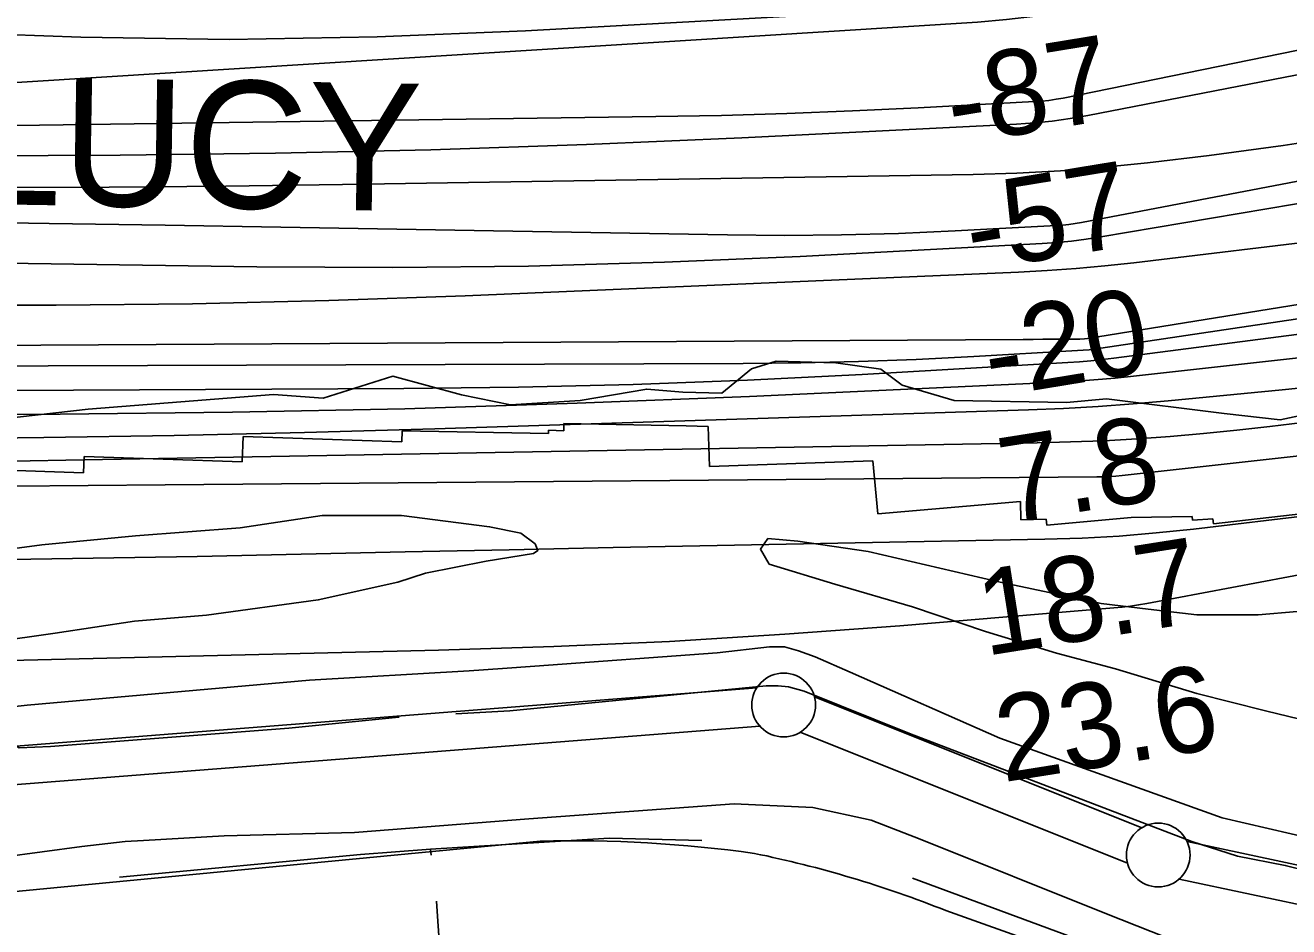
# Model space of a CAD drawing. Extents: x 3508733 to 3546731, y 546897 to 572481.
# Drawn here: x 3535009 to 3536000, y 561954 to 562661 of the extents above; entities that cross this region are included whole.
import ezdxf

# ---------------------------------------------------------------- set-up
doc = ezdxf.new("R2010")
doc.units = 0
for name, color, linetype in [('V-FLOD-BASE', 7, 'Continuous'), ('V-LEVE-TOET', 7, 'Continuous'), ('V-RIVR-EDGE', 7, 'Continuous'), ('V-RIVR-RANG', 7, 'Continuous'), ('V-ROAD-CNTR', 7, 'Continuous'), ('V-RRAP-RVMT', 7, 'Continuous'), ('V-RRAP-RVMT-IDEN', 7, 'Continuous'), ('V-SITE-VEGE', 7, 'Continuous'), ('V-SURV-LINE', 7, 'Continuous'), ('V-TOPO-DPTH', 7, 'Continuous'), ('V-TOPO-MAJR', 7, 'Continuous'), ('V-TOPO-MINR', 7, 'Continuous'), ('V-TOPO-SHOR', 7, 'Continuous'), ('V-TOPO-WATR', 7, 'Continuous')]:
    doc.layers.add(name, color=color, linetype=linetype)

msp = doc.modelspace()

# ---------------------------------------------------------------- linework, layer by layer
at = {"layer": 'V-FLOD-BASE'}
for points in [[(3535346.74, 562120.84), (3535389.06, 562123.27), (3535590.19, 562142.96), (3535599.58, 562142.86), (3535607.8, 562142.19), (3535620.1, 562138.54), (3535702.6, 562105.39), (3535924.4, 562020.89), (3535960.12, 562009.37), (3535997.65, 562001.94), (3536053.9, 561987.85), (3536085.55, 561980.48), (3536112.54, 561977.27), (3536164.23, 561976.16), (3536242.97, 561977.7), (3536287.05, 561979.61)], [(3532710.45, 562040.61), (3532907.8, 562036.26), (3533054.05, 562032.42), (3533261.96, 562026.2), (3533512.77, 562021.89), (3533708.99, 562021.66), (3533810.05, 562022.98), (3533971.6, 562021.93), (3534038.02, 562025.37), (3534206.16, 562037.17), (3534387.26, 562051.78), (3534513.1, 562063.43), (3534724.18, 562080.08), (3534928.17, 562093.28), (3534994.62, 562099.66), (3535003.96, 562094.28), (3535028.65, 562095.2), (3535215.62, 562109.75), (3535302.06, 562118.27), (3535302.12, 562118.28)]]:
    msp.add_lwpolyline(points, dxfattribs=at)
at = {"layer": 'V-LEVE-TOET'}
for points in [[(3536056.52, 562014.26), (3535948.09, 562039.45), (3535773.65, 562101.73), (3535656.09, 562153.45), (3535628.6, 562165.48), (3535615.73, 562170.31), (3535604.6, 562173.36), (3535592.85, 562173.48), (3535551.67, 562168.61), (3535408.81, 562158.32), (3535383.24, 562156.54), (3535357.07, 562154.73), (3535231.86, 562147.19), (3535010.18, 562127.7), (3534833.15, 562108.35), (3534677.93, 562096.41), (3534491.56, 562083.03), (3534318.08, 562065.99), (3534147.58, 562053.63), (3533987.15, 562049.38), (3533933.12, 562050.52)], [(3534380.39, 561953.86), (3534559.73, 561969.66), (3534741.97, 561980.73), (3534928.4, 561999.99), (3535053.12, 562016.94), (3535087.23, 562020.7), (3535101.67, 562021.54), (3535164.94, 562025.2), (3535267.19, 562027.8), (3535404.07, 562038.52), (3535565.16, 562050.39), (3535626.81, 562047.41), (3535672.54, 562037.55), (3535711.16, 562022.47), (3535857.44, 561964), (3535975.05, 561917.57)]]:
    msp.add_lwpolyline(points, dxfattribs=at)
at = {"layer": 'V-RIVR-EDGE'}
msp.add_lwpolyline([(3534866.07, 562338.1), (3535058.23, 562359.84), (3535203.54, 562371.48), (3535242.55, 562368.39), (3535297.22, 562385.66), (3535351.22, 562371.12), (3535389.62, 562363.22), (3535444.26, 562366.69), (3535496.51, 562375.56), (3535524.72, 562373.09), (3535555.33, 562372.42), (3535578.79, 562391.57), (3535598.02, 562397.52), (3535644.84, 562396.21), (3535680.24, 562391.32), (3535697.02, 562378.67), (3535737.81, 562366.56), (3535826.06, 562365.14), (3535857.28, 562368.07), (3535949.71, 562356.43), (3535993.52, 562351.52), (3536065.59, 562366.95)], dxfattribs=at)
at = {"layer": 'V-ROAD-CNTR'}
for points in [[(3535412.83, 562021.11), (3534946.57, 561976.32), (3534572.86, 561951.67), (3534297.18, 561926.9), (3534032.81, 561905.44)], [(3535875.71, 561915.18), (3535731.32, 561966.59)]]:
    msp.add_lwpolyline(points, dxfattribs=at)
for centre, radius, start, end in [((3535436.77, 560972.05), 1049.34, 82.09715, 91.30692), ((3535401.25, 561134.53), 895.13, 68.36224, 78.41314)]:
    msp.add_arc(centre, radius, start, end, dxfattribs=at)
at = {"layer": 'V-RRAP-RVMT'}
for p, q in [((3535304.22, 562334.23), (3535304.53, 562342.94)), ((3535304.53, 562342.94), (3535419.28, 562340.82)), ((3535419.28, 562340.82), (3535419.34, 562343.39)), ((3535419.34, 562343.39), (3535431.32, 562342.98)), ((3535431.32, 562342.98), (3535431.49, 562348.53)), ((3535431.49, 562348.53), (3535527.33, 562346.75)), ((3535527.33, 562346.75), (3535544.61, 562346.15)), ((3535544.61, 562346.15), (3535545.79, 562314.95)), ((3535178.9, 562318.53), (3535179.72, 562338.43)), ((3535179.72, 562338.43), (3535304.22, 562334.23)), ((3535054.51, 562309.97), (3535054.98, 562322.72)), ((3535054.98, 562322.72), (3535178.9, 562318.53)), ((3534931.1, 562314.19), (3535054.51, 562309.97)), ((3535545.79, 562314.95), (3535674, 562319.39)), ((3535674, 562319.39), (3535677.82, 562277.65)), ((3535677.82, 562277.65), (3535789.84, 562287.54)), ((3535789.84, 562287.54), (3535790.11, 562273.09)), ((3535790.11, 562273.09), (3535809.94, 562273.49)), ((3535809.94, 562273.49), (3535810.38, 562268.76)), ((3535810.38, 562268.76), (3535876.7, 562274.81)), ((3535876.7, 562274.81), (3535924.59, 562275.76)), ((3535924.59, 562275.76), (3535924.78, 562272.68)), ((3535924.78, 562272.68), (3535940.9, 562273.76)), ((3535940.9, 562273.76), (3535941.36, 562269.85)), ((3535941.36, 562269.85), (3536021.35, 562279.16))]:
    msp.add_line(p, q, dxfattribs=at)
at = {"layer": 'V-SITE-VEGE'}
for points in [[(3534952.88, 562244.26), (3535021.71, 562253.54), (3535095.22, 562260.44), (3535177.53, 562266.65), (3535241.67, 562276.57), (3535303.94, 562276.53), (3535373.17, 562267.6), (3535397.8, 562262.65), (3535408.88, 562254.31), (3535411.17, 562249), (3535407.62, 562246.69), (3535370.55, 562240.6), (3535322.87, 562231.1), (3535301.06, 562224.27), (3535238.65, 562210.22), (3535150.98, 562198.18), (3535094.54, 562193.47), (3535032.17, 562184.11), (3534982.16, 562176.98)], [(3536009.07, 562116.61), (3535982.11, 562123.35), (3535928.2, 562136.83), (3535864.36, 562156.27), (3535818.08, 562168.49), (3535762.44, 562185.51), (3535705.06, 562204.89), (3535644.14, 562222.55), (3535592.6, 562238.34), (3535585.67, 562250.17), (3535591.63, 562258.33), (3535615.11, 562256.33), (3535670.25, 562248.13), (3535771.65, 562224.78), (3535853.13, 562207.5), (3535890.1, 562203.01), (3535928.24, 562198.51), (3535976.42, 562198.61), (3536006.99, 562201.24)]]:
    msp.add_lwpolyline(points, dxfattribs=at)
at = {"layer": 'V-SURV-LINE'}
for points in [[(3533967.89, 562014.2), (3535582.88, 562141.23)], [(3535628.11, 562134.33), (3535884.95, 562031.5)], [(3535585.23, 562111.32), (3533970.23, 561984.29)], [(3535873.78, 562003.66), (3535616.94, 562106.49)], [(3535920.59, 562020.68), (3536090.87, 561984.55)], [(3536084.63, 561955.21), (3535914.35, 561991.33)]]:
    msp.add_lwpolyline(points, dxfattribs=at)
for centre in [(3535603.97, 562127.84), (3535897.92, 562010.15)]:
    msp.add_circle(centre, 25, dxfattribs=at)
at = {"layer": 'V-TOPO-DPTH'}
for points in [[(3536504.22, 562604.88), (3535853, 562494.94), (3535841.49, 562493.2), (3535829.95, 562491.72), (3535818.36, 562490.64), (3535806.74, 562489.82), (3535616.96, 562479.7), (3535510.41, 562475.1), (3535403.84, 562471.95), (3535297.22, 562470.97), (3535190.57, 562471.44), (3534795.52, 562477.17), (3534753.11, 562477.76), (3534710.7, 562478.3), (3534668.29, 562478.78), (3534625.88, 562479.22), (3534583.15, 562479.64), (3534519.37, 562480.23), (3534455.59, 562480.79), (3534391.82, 562481.3), (3534328.04, 562481.78), (3533592.42, 562487)], [(3536504.22, 562604.88), (3535853, 562494.94), (3535841.49, 562493.2), (3535829.95, 562491.72), (3535818.36, 562490.64), (3535806.74, 562489.82), (3535616.96, 562479.7), (3535510.41, 562475.1), (3535403.84, 562471.95), (3535297.22, 562470.97), (3535190.57, 562471.44), (3534795.52, 562477.17), (3534753.11, 562477.76), (3534710.7, 562478.3), (3534668.29, 562478.78), (3534625.88, 562479.22), (3534583.15, 562479.64), (3534519.37, 562480.23), (3534455.59, 562480.79), (3534391.82, 562481.3), (3534328.04, 562481.78), (3533592.42, 562487)], [(3533862.28, 562416.56), (3534004.12, 562415.25), (3534145.97, 562413.99), (3534287.82, 562412.82), (3534429.66, 562411.71), (3534641.17, 562410.11), (3534677.26, 562409.86), (3534713.36, 562409.65), (3534749.45, 562409.5), (3534785.55, 562409.38), (3534821.64, 562409.34), (3534857.74, 562409.35), (3534893.84, 562409.46), (3534929.93, 562409.62), (3535792.04, 562414.58), (3535799.65, 562414.62), (3535807.25, 562414.67), (3535814.86, 562414.71), (3535822.46, 562414.76), (3535835.37, 562414.83), (3535836.52, 562414.85), (3535839.96, 562414.98), (3535842.49, 562415.15), (3536790.17, 562568.34)], [(3533862.28, 562416.56), (3534004.12, 562415.25), (3534145.97, 562413.99), (3534287.82, 562412.82), (3534429.66, 562411.71), (3534641.17, 562410.11), (3534677.26, 562409.86), (3534713.36, 562409.65), (3534749.45, 562409.5), (3534785.55, 562409.38), (3534821.64, 562409.34), (3534857.74, 562409.35), (3534893.84, 562409.46), (3534929.93, 562409.62), (3535792.04, 562414.58), (3535799.65, 562414.62), (3535807.25, 562414.67), (3535814.86, 562414.71), (3535822.46, 562414.76), (3535835.37, 562414.83), (3535836.52, 562414.85), (3535839.96, 562414.98), (3535842.49, 562415.15), (3536790.17, 562568.34)], [(3536039.54, 562494.04), (3535878.65, 562474.65), (3535856.07, 562472.19), (3535833.47, 562470.09), (3535810.82, 562468.51), (3535788.14, 562467.28), (3535353.95, 562448.85), (3535247.02, 562445.12), (3535140.07, 562442.45), (3535033.09, 562441.39), (3534926.09, 562441.4), (3534762.65, 562442.64), (3534737.36, 562442.83), (3534712.07, 562443.04), (3534686.77, 562443.26), (3534661.48, 562443.48), (3534009.83, 562449.45), (3533932.07, 562450.16)], [(3533932.07, 562450.16), (3534009.83, 562449.45), (3534661.48, 562443.48), (3534686.77, 562443.26), (3534712.07, 562443.04), (3534737.36, 562442.83), (3534762.65, 562442.64), (3534926.09, 562441.4), (3535033.09, 562441.39), (3535140.07, 562442.45), (3535247.02, 562445.12), (3535353.95, 562448.85), (3535788.14, 562467.28), (3535810.82, 562468.51), (3535833.47, 562470.09), (3535856.07, 562472.19), (3535878.65, 562474.65), (3536039.54, 562494.04)], [(3536178.12, 562440.74), (3535863.07, 562399.79), (3535854.08, 562398.72), (3535845.07, 562397.77), (3535836.05, 562397.03), (3535827.01, 562396.41), (3535665.5, 562387.12), (3535575.67, 562382.67), (3535485.82, 562379.17), (3535395.92, 562377.08), (3535305.99, 562375.95), (3534735.27, 562373.24), (3534725.01, 562373.2), (3534714.76, 562373.15), (3534704.51, 562373.11), (3534694.25, 562373.07), (3534490.36, 562372.29), (3534378.15, 562372), (3534265.95, 562371.89), (3534153.75, 562372.08), (3534041.55, 562372.45), (3533601.11, 562374.45)], [(3533601.11, 562374.45), (3534041.55, 562372.45), (3534153.75, 562372.08), (3534265.95, 562371.89), (3534378.15, 562372), (3534490.36, 562372.29), (3534694.25, 562373.07), (3534704.51, 562373.11), (3534714.76, 562373.15), (3534725.01, 562373.2), (3534735.27, 562373.24), (3535305.99, 562375.95), (3535395.92, 562377.08), (3535485.82, 562379.17), (3535575.67, 562382.67), (3535665.5, 562387.12), (3535827.01, 562396.41), (3535836.05, 562397.03), (3535845.07, 562397.77), (3535854.08, 562398.72), (3535863.07, 562399.79), (3536178.12, 562440.74)], [(3536067.23, 562382.22), (3535995.17, 562374.91), (3535905.67, 562366.33), (3535878.3, 562363.97), (3535850.91, 562361.96), (3535823.48, 562360.47), (3535796.04, 562359.32), (3535330.24, 562344.39), (3535227.93, 562341.5), (3535125.61, 562339.12), (3535023.28, 562337.52), (3534920.93, 562336.44), (3534757.58, 562335.33), (3534736.9, 562335.18), (3534716.23, 562335.03), (3534695.55, 562334.87), (3534674.87, 562334.71), (3533882.99, 562328.22)], [(3536067.23, 562382.22), (3535995.17, 562374.91), (3535905.67, 562366.33), (3535878.3, 562363.97), (3535850.91, 562361.96), (3535823.48, 562360.47), (3535796.04, 562359.32), (3535330.24, 562344.39), (3535227.93, 562341.5), (3535125.61, 562339.12), (3535023.28, 562337.52), (3534920.93, 562336.44), (3534757.58, 562335.33), (3534736.9, 562335.18), (3534716.23, 562335.03), (3534695.55, 562334.87), (3534674.87, 562334.71), (3533882.99, 562328.22)], [(3534997.78, 562299.42), (3535058.15, 562299.88), (3535118.53, 562300.38), (3535849.72, 562306.66), (3535854.72, 562306.78), (3535859.71, 562307), (3535864.69, 562307.37), (3535869.66, 562307.85), (3536178.34, 562342.07)]]:
    msp.add_lwpolyline(points, dxfattribs=at)
at = {"layer": 'V-TOPO-MAJR'}
for points in [[(3534936.08, 562655.7), (3535052.41, 562651.55), (3535168.73, 562649.88), (3535285.05, 562651.96), (3535401.37, 562656.52), (3535766.47, 562676.73), (3535783.08, 562678.07), (3535799.6, 562679.98), (3535816.01, 562682.72), (3535832.33, 562686.03), (3536334.06, 562801.04)], [(3534913.7, 562507.22), (3535027.54, 562505.5), (3535118.48, 562504.08), (3535209.42, 562502.62), (3535300.37, 562501.09), (3535391.31, 562499.5), (3535559.98, 562496.5), (3535604.66, 562496.18), (3535649.33, 562496.49), (3535693.98, 562497.74), (3535738.62, 562499.62), (3535818.02, 562503.8), (3535822.94, 562504.16), (3535827.84, 562504.65), (3535832.72, 562505.35), (3535837.58, 562506.17), (3536547.27, 562641.56)]]:
    msp.add_lwpolyline(points, dxfattribs=at)
at = {"layer": 'V-TOPO-MINR'}
for points in [[(3533931.78, 562646.66), (3534007.98, 562642.14), (3534662.9, 562605.64), (3534684.4, 562604.61), (3534705.91, 562603.79), (3534727.43, 562603.29), (3534748.95, 562603.02), (3534770.47, 562603.12), (3534791.99, 562603.52), (3534813.49, 562604.36), (3534834.98, 562605.49), (3535756.08, 562663.44), (3535778.85, 562665.42), (3535801.52, 562668.1), (3535824.04, 562671.86), (3535846.45, 562676.32), (3536721.03, 562872.16)], [(3533939.82, 562567.51), (3534070.5, 562563.77), (3534201.21, 562561.35), (3534331.94, 562559.81), (3534671.43, 562557.52), (3534689.55, 562557.43), (3534707.67, 562557.39), (3534725.78, 562557.4), (3534743.9, 562557.46), (3535083.15, 562559.19), (3535205.19, 562560.64), (3535327.19, 562563.17), (3535449.16, 562567.34), (3535571.09, 562572.61), (3535786.58, 562583.36), (3535800.71, 562584.37), (3535814.79, 562585.78), (3535828.8, 562587.78), (3535842.77, 562590.19), (3536911.98, 562797.95)], [(3533566.37, 562617.21), (3534301.26, 562585.73), (3534368.83, 562583.21), (3534436.41, 562581.18), (3534504.01, 562579.9), (3534571.62, 562579.11), (3534691.63, 562578.37), (3534699.24, 562578.35), (3534706.86, 562578.35), (3534714.47, 562578.41), (3534722.08, 562578.49), (3535503.67, 562589.29), (3535555.12, 562590.3), (3535606.57, 562591.72), (3535657.99, 562593.75), (3535709.4, 562596.18), (3535800.93, 562601.05), (3535806.55, 562601.48), (3535812.14, 562602.07), (3535817.71, 562602.9), (3535823.25, 562603.9), (3536055.11, 562651.06)], [(3533592.42, 562487), (3534328.04, 562481.78), (3534391.82, 562481.3), (3534455.59, 562480.79), (3534519.37, 562480.23), (3534583.15, 562479.64), (3534625.88, 562479.22), (3534668.29, 562478.78), (3534710.7, 562478.3), (3534753.11, 562477.76), (3534795.52, 562477.17), (3535190.57, 562471.44), (3535297.22, 562470.97), (3535403.84, 562471.95), (3535510.41, 562475.1), (3535616.96, 562479.7), (3535806.74, 562489.82), (3535818.36, 562490.64), (3535829.95, 562491.72), (3535841.49, 562493.2), (3535853, 562494.94), (3536504.22, 562604.88)], [(3533680.62, 562539.52), (3534649.1, 562534.39), (3534678.83, 562534.25), (3534708.56, 562534.11), (3534738.29, 562534.01), (3534768.02, 562533.91), (3534891.63, 562533.58), (3534983.17, 562533.58), (3535074.7, 562533.93), (3535166.23, 562534.79), (3535257.76, 562535.99), (3535752.64, 562543.87), (3535786.95, 562544.94), (3535821.21, 562546.72), (3535855.41, 562549.55), (3535889.55, 562553.08), (3535937.85, 562558.82), (3535995.96, 562566.58), (3536053.89, 562575.46)], [(3533862.28, 562416.56), (3534004.12, 562415.25), (3534145.97, 562413.99), (3534287.82, 562412.82), (3534429.66, 562411.71), (3534641.17, 562410.11), (3534677.26, 562409.86), (3534713.36, 562409.65), (3534749.45, 562409.5), (3534785.55, 562409.38), (3534821.64, 562409.34), (3534857.74, 562409.35), (3534893.84, 562409.46), (3534929.93, 562409.62), (3535792.04, 562414.58), (3535799.65, 562414.62), (3535807.25, 562414.67), (3535814.86, 562414.71), (3535822.46, 562414.76), (3535835.37, 562414.83), (3535836.52, 562414.85), (3535839.96, 562414.98), (3535842.49, 562415.15), (3536790.17, 562568.34)], [(3533576.61, 562399.9), (3534691.2, 562392.94), (3534695, 562392.92), (3534698.8, 562392.9), (3534702.6, 562392.9), (3534706.4, 562392.9), (3534713.27, 562392.91), (3534714, 562392.91), (3534714.36, 562392.91), (3534714.73, 562392.92), (3535572.24, 562395.65), (3535617.52, 562396.16), (3535662.78, 562397.16), (3535708.02, 562398.89), (3535753.25, 562401.11), (3535834.52, 562405.76), (3535839.09, 562406.08), (3535843.66, 562406.49), (3535848.21, 562407.02), (3535852.76, 562407.63), (3536469.23, 562499.46)], [(3533932.07, 562450.16), (3534009.83, 562449.45), (3534661.48, 562443.48), (3534686.77, 562443.26), (3534712.07, 562443.04), (3534737.36, 562442.83), (3534762.65, 562442.64), (3534926.09, 562441.4), (3535033.09, 562441.39), (3535140.07, 562442.45), (3535247.02, 562445.12), (3535353.95, 562448.85), (3535788.14, 562467.28), (3535810.82, 562468.51), (3535833.47, 562470.09), (3535856.07, 562472.19), (3535878.65, 562474.65), (3536039.54, 562494.04)], [(3533792.69, 562133.7), (3535332.96, 562170.73), (3535423.63, 562173.71), (3535514.25, 562177.74), (3535604.78, 562183.36), (3535695.25, 562190.04), (3535863.1, 562203.92), (3535869.6, 562204.56), (3535876.07, 562205.33), (3535882.52, 562206.3), (3535888.96, 562207.41), (3537178.66, 562450.07)], [(3533601.11, 562374.45), (3534041.55, 562372.45), (3534153.75, 562372.08), (3534265.95, 562371.89), (3534378.15, 562372), (3534490.36, 562372.29), (3534694.25, 562373.07), (3534704.51, 562373.11), (3534714.76, 562373.15), (3534725.01, 562373.2), (3534735.27, 562373.24), (3535305.99, 562375.95), (3535395.92, 562377.08), (3535485.82, 562379.17), (3535575.67, 562382.67), (3535665.5, 562387.12), (3535827.01, 562396.41), (3535836.05, 562397.03), (3535845.07, 562397.77), (3535854.08, 562398.72), (3535863.07, 562399.79), (3536178.12, 562440.74)], [(3533938.89, 562349.38), (3534675.75, 562353.69), (3534695.63, 562353.8), (3534715.5, 562353.92), (3534735.38, 562354.04), (3534755.25, 562354.16), (3535036.22, 562355.82), (3535171.52, 562357.44), (3535306.78, 562360.13), (3535442.01, 562364.44), (3535577.21, 562369.83), (3535814.05, 562380.69), (3535830.79, 562381.62), (3535847.51, 562382.77), (3535864.21, 562384.25), (3535880.89, 562385.95), (3536083.39, 562408.53)], [(3534997.78, 562299.42), (3535058.15, 562299.88), (3535118.53, 562300.38), (3535849.72, 562306.66), (3535854.72, 562306.78), (3535859.71, 562307), (3535864.69, 562307.37), (3535869.66, 562307.85), (3536178.34, 562342.07)], [(3534998.48, 562319.08), (3535054.78, 562320), (3535802.98, 562333.39), (3535829.12, 562334.1), (3535855.24, 562335.13), (3535881.33, 562336.64), (3535907.41, 562338.47), (3535933.46, 562340.74), (3535959.49, 562343.27), (3535985.47, 562346.18), (3536011.42, 562349.34)], [(3533884.7, 562243.86), (3534018.35, 562240.33), (3534143.27, 562237.73), (3534268.2, 562236.07), (3534393.14, 562235.8), (3534518.08, 562236.47), (3534898.85, 562240.65), (3534980.49, 562241.69), (3535062.12, 562242.91), (3535143.75, 562244.4), (3535225.38, 562246.08), (3535307, 562247.87), (3535388.63, 562249.6), (3535470.26, 562251.25), (3535551.88, 562252.85), (3535808.98, 562257.78), (3535838.18, 562258.77), (3535867.33, 562260.34), (3535896.43, 562262.76), (3535925.49, 562265.76), (3536022.17, 562277.17)]]:
    msp.add_lwpolyline(points, dxfattribs=at)
at = {"layer": 'V-TOPO-SHOR'}
for points in [[(3535539.63, 562021.58), (3535466.92, 562023.48), (3535326.82, 562014.79)], [(3535082.75, 561992.75), (3535271.94, 562010.67), (3535326.82, 562014.79), (3535327.36, 562010.04)], [(3535705, 561992.06), (3535848.76, 561938.88), (3535939.46, 561909.57), (3536002.69, 561892.99), (3536069.85, 561881.03), (3536112.99, 561877.87), (3536224.21, 561876.75), (3536318.01, 561883.97), (3536425.87, 561896.49)], [(3535331.46, 561973.9), (3535353.44, 561646.99), (3535385.5, 561240.65), (3535399.44, 561042.17), (3535395.52, 561039.48), (3535255.92, 561002.39), (3535009.87, 560937.99), (3535009.65, 560931.36)]]:
    msp.add_lwpolyline(points, dxfattribs=at)
at = {"layer": 'V-TOPO-WATR'}
msp.add_lwpolyline([(3533882.99, 562328.22), (3534674.87, 562334.71), (3534695.55, 562334.87), (3534716.23, 562335.03), (3534736.9, 562335.18), (3534757.58, 562335.33), (3534920.93, 562336.44), (3535023.28, 562337.52), (3535125.61, 562339.12), (3535227.93, 562341.5), (3535330.24, 562344.39), (3535796.04, 562359.32), (3535823.48, 562360.47), (3535850.91, 562361.96), (3535878.3, 562363.97), (3535905.67, 562366.33), (3535995.17, 562374.91), (3536067.23, 562382.22)], dxfattribs=at)

# ---------------------------------------------------------------- texts
at = {"layer": 'V-RIVR-RANG'}
for s, rotation, p in [('-87', 9.29708, (3535737.18, 562566.86)), ('-57', 9.29708, (3535752.05, 562467.97)), ('-20', 9.29708, (3535766.41, 562368.99)), ('7.8', 9.01833, (3535778.98, 562270.13)), ('18.7', 9.01833, (3535762.06, 562166.2)), ('23.6', 9.01833, (3535776.15, 562067.18))]:
    msp.add_text(s, height=67, rotation=rotation, dxfattribs=at).set_placement(p)
at = {"layer": 'V-RRAP-RVMT-IDEN'}
msp.add_text('LUCY', height=100, rotation=359.05533, dxfattribs=at).set_placement((3534962.45, 562520.9))

doc.saveas('drawing.dxf')
